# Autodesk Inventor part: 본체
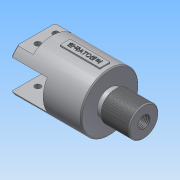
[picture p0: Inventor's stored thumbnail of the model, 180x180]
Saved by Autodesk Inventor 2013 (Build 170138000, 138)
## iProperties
Created: 2019-02
Part Number: 본체
Material: 알루미늄 6061
Document SubType Name: Modeling
Designer: Administrator
Density: 2.71 g/cm^3
Mass: 347.679 g
Surface Area: 294.887 cm^2
Volume: 128.295 cm^3
Author: Administrator
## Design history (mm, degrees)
sketch "스케치1"
  geometry: 1 further point
sketch "스케치2"
  geometry: L1 (-54, 0)-(-54, 29); L2 (-54, 29)-(20, 29); L3 (20, 29)-(20, 13); L4 (20, 13)-(25, 13); L5 (25, 13)-(25, 15); L6 (25, 15)-(54, 15); L7 (54, 15)-(54, 0); L8 (54, 0)-(-54, 0); 2 further points
  constraints: 16 end point, 4 parallel, 1 coincident, 1 horizontal, 1 midpoint, 1 vertical
  dimensions: "d2" = 30 diameter of L6 L8; "d3" = 26 diameter of L4 L8; "d4" = 58 diameter of L2 L8; "d5" = 74 distance of L1.end L2.end; "d6" = 34 horizontal distance of L6.end L2.end; "d7" = 5 distance of L3.end L4.end
revolve "회전1" sketch "스케치2" stored, may be unused: angle "d8" = 90 deg
sketch "스케치3"
  geometry: L1 (15, 38.25)-(-15, 38.25); L2 (-15, 38.25)-(-15, -38.036); L3 (-15, -38.036)-(15, -38.036); L4 (15, -38.036)-(15, 38.25); C1 r 29 at (0, 0) reference; 1 further point
  constraints: 8 end point, 2 parallel, 1 horizontal, 1 midpoint, 1 perpendicular, 1 vertical alignment
  dimensions: "d9" = 30 distance of L1.start L1.end
extrude "돌출1" cut sketch "스케치3" distance "d11" = 36; taper "d12" = 0 deg
sketch "스케치4"
  geometry: L1 (15, 24.819)-(15, -24.819) reference; L2 (-15, -24.819)-(-15, 24.819) reference; L3 (15, 24.819)-(15, -24.819) reference; L4 (39.665, 38.613)-(22, 38.613); L5 (22, 38.613)-(22, -30.913); L6 (22, -30.913)-(39.665, -30.913); L7 (39.665, -30.913)-(39.665, 38.613); L8 (-22, 58.316)-(-38.532, 58.316); L9 (-38.532, 58.316)-(-38.532, -42.69); L10 (-38.532, -42.69)-(-22, -42.69); L11 (-22, -42.69)-(-22, 58.316); A1 r 29 centre (0, 0) between (-15, 24.819) and (-15, -24.819) reference; A2 r 29 centre (0, 0) between (15, -24.819) and (15, 24.819) reference
  constraints: 16 end point, 4 parallel, 2 horizontal, 2 perpendicular
  dimensions: "d13" = 7 distance between parallel lines of L11 L2; "d14" = 7 distance between parallel lines of L5 L1
extrude "돌출2" cut sketch "스케치4" distance "d15" = 16; taper "d16" = 0 deg
sketch "스케치5"
  geometry: L1 (0, 0)-(0, 37.789) reference; L2 (36, 43.714)-(0, 43.714) reference; L3 (0, -5.925)-(36, -5.925) reference; L4 (36, 47.894)-(74, 47.894) reference; L5 (74, -10.106)-(74, 47.894) reference; L6 (0, 0)-(16, 0) reference; L7 (16, 0)-(16, 37.789) reference; L8 (16, 37.789)-(0, 37.789) reference; L9 (0, 37.789)-(0, 43.714) reference; L10 (0, 43.714)-(36, 43.714) reference; L11 (36, 43.714)-(36, 43.714) reference; L12 (36, 43.714)-(0, 43.714) reference; L13 (0, 43.714)-(0, 37.789) reference; L14 (0, 37.789)-(16, 37.789) reference; L15 (16, 37.789)-(16, 0) reference; L16 (16, 0)-(0, 0) reference; L17 (0, 0)-(0, -5.925) reference; L18 (0, -5.925)-(36, -5.925) reference; L19 (36, -5.925)-(36, -5.925) reference; L20 (36, -5.925)-(0, -5.925) reference; L21 (0, -5.925)-(0, 0) reference; L22 (36, -10.106)-(74, -10.106) reference; L23 (0, 18.894)-(108, 18.894); L24 (108, 3.894)-(108, 33.894) reference; L25 (79, 3.894)-(79, 33.894) reference; C1 r 3 at (9, 29.658); C2 r 3 at (9, 11.658); 1 further point
  constraints: 2 centre point, 2 end point, 2 midpoint, 1 parallel
  dimensions: "d17" = 6 diameter of C1; "d20" = 6 diameter of C2; "d21" = 18 distance of C2.centre C1.centre; "d22" = 9 distance from line of L1 C2.centre; "d25" = 29 distance between parallel lines of L23 L22
extrude "돌출3" cut sketch "스케치5" stored distance "d26" = 16; taper "d27" = 0 deg
sketch "스케치6"
  geometry: L1 (20, -29)-(-18, -29) reference; L2 (-18, -29)-(-18, 29) reference; L3 (-18, 29)-(20, 29) reference; L4 (20, 29)-(20, 13) reference; L5 (20, 13)-(25, 13) reference; L6 (25, 13)-(25, 15) reference; L7 (25, 15)-(54, 15) reference; L8 (54, 15)-(54, -15) reference; L9 (54, -15)-(25, -15) reference; L10 (25, -15)-(25, -13) reference; L11 (25, -13)-(20, -13) reference; L12 (20, -13)-(20, -29) reference; L13 (-18, 14)-(-15.35, 14); L14 (-15.35, 14)-(-15.35, 17); L15 (-15.35, 17)-(-10.65, 17); L16 (-10.65, 17)-(-10.65, 14); L17 (-10.65, 14)-(-6.35, 14); L18 (-6.35, 14)-(-6.35, 17); L19 (-6.35, 17)-(-1.65, 17); L20 (-1.65, 17)-(-1.65, 14); L21 (-1.65, 14)-(2, 14); L22 (2, 14)-(2, 16); L23 (2, 16)-(9, 16); L24 (9, 16)-(9, 4); L25 (9, 4)-(32, 4); L26 (-18, 0)-(54, 0); L27 (-18, 0)-(-18, 14); L28 (-13, 17)-(-13, 0); L29 (-4, 17)-(-4, 0); L30 (32, 4)-(32, 0); 1 further point
  constraints: 36 end point, 9 parallel, 6 perpendicular, 5 collinear, 4 midpoint, 4 point on line, 1 horizontal alignment
  dimensions: "d28" = 4.7 distance of L14.end L15.end; "d30" = 4.7 distance of L18.end L19.end; "d32" = 34 diameter of L15 L26; "d33" = 28 diameter of L17 L26; "d34" = 8 diameter of L25 L26; "d35" = 32 diameter of L23 L26; "d36" = 27 distance between parallel lines of L24 L2; "d37" = 20 distance between parallel lines of L2 L22; "d38" = 5 distance from line of L2 L28.start; "d39" = 9 distance between parallel lines of L28 L29; "d40" = 28 diameter of L13 L26; "d60" = 22 distance between parallel lines of L8 L30
revolve "회전2" sketch "스케치6" stored, may be unused: angle "d42" = 90 deg
feature "스레드1" dims "d43" = 10, "d44" = 0
node "작업 평면1"
sketch "스케치7"
  geometry: L1 (-25, 5)-(15, 5); L2 (15, 5)-(15, -5); L3 (15, -5)-(-25, -5); L4 (-25, -5)-(-25, 5); L5 (20, -29)-(20, 29) reference; 2 further points
  constraints: 8 end point, 2 parallel, 1 horizontal, 1 horizontal alignment, 1 midpoint, 1 perpendicular
  dimensions: "d46" = 40 distance of L1.start L1.end; "d48" = 10 distance of L3.end L1.start; "d49" = 5 distance between parallel lines of L5 L2
node "작업 평면2"
sketch "스케치8"
  geometry: 1 further point
sketch "스케치9"
  geometry: L1 (-25, 5)-(15, 5); L2 (15, 5)-(15, -5); L3 (15, -5)-(-25, -5); L4 (-25, -5)-(-25, 5); L5 (20, -29)-(20, 29) reference; 2 further points
  constraints: 8 end point, 2 parallel, 1 horizontal, 1 horizontal alignment, 1 midpoint, 1 perpendicular
  dimensions: "d51" = 5 distance between parallel lines of L5 L2; "d52" = 40 distance of L1.start L1.end; "d53" = 10 distance of L3.end L1.start
extrude "돌출4" join sketch "스케치9" stored distance "d54" = 16; taper "d55" = 0 deg
sketch "스케치10"
  geometry: L1 (-25, 5)-(15, 5) reference; L2 (-25, -5)-(-25, 5) reference; L3 (15, -5)-(-25, -5) reference; L4 (15, 5)-(15, -5) reference; 2 further points
  constraints: 1 other
  dimensions: "d56" = 20 distance from line of point (-5, 0) L2; "d57" = 5 distance from line of L3 point (-5, 0)
feature "엠보싱1" sketch "스케치10" dims "d58" = 0.5, "d59" = 0
sketch "스케치11"
  geometry: C1 r 15 at (0, 0) reference; 1 further point
  constraints: 1 coincident
hole "구멍1" sketch "스케치11" at (0, 0) diameter "d61" = 12.376; stored, may be unused: countersink angle "d65" = 82 deg, drill point angle "d67" = 118 deg; dims "d62" = 18, "d63" = 3.023, "d64" = 2, "d66" = 22
sketch "스케치12"
  geometry: 1 further point
sketch "스케치13"
  geometry: 1 further point
sketch "스케치14"
  geometry: 1 further point
chamfer "모따기1" distance "d68" = 1; stored, may be unused: second distance "d69" = 2, angle "d70" = 45 deg
chamfer "모따기2" distance "d71" = 1; stored, may be unused: second distance "d72" = 2, angle "d73" = 45 deg
chamfer "모따기3" distance "d74" = 1; stored, may be unused: second distance "d75" = 2, angle "d76" = 45 deg
fillet "모깎기1" dims "d77" = 0.8
node "솔리드1"
node "투영된 루프1"
node "투영된 루프2"
node "투영된 루프3"
node "투영된 루프4"
node "투영된 루프5"
node "절단 모서리 투영1"
